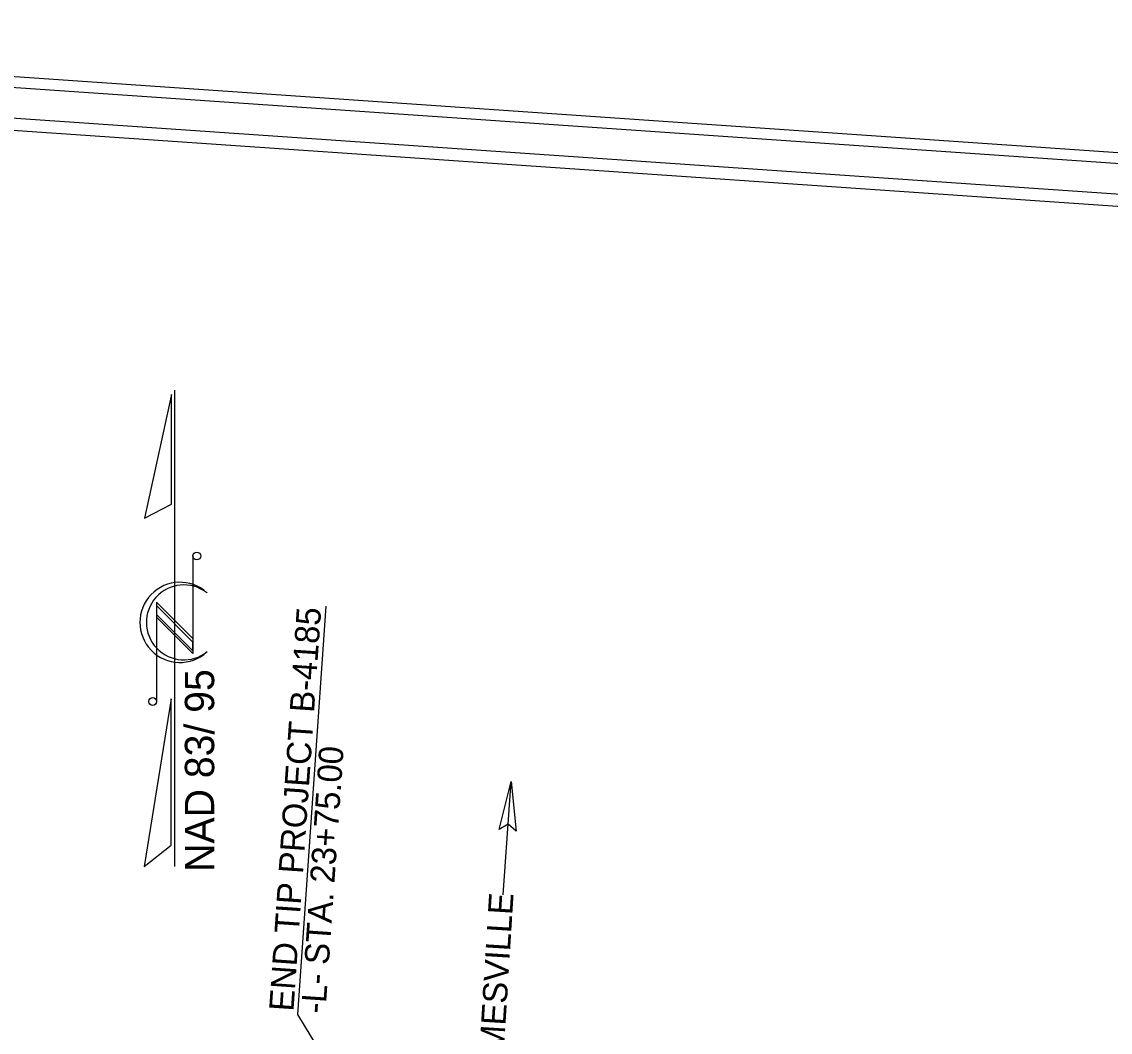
# Model space of a CAD drawing. Extents: x 2598107 to 2605763, y 726018 to 731166.
# Drawn here: x 2599109 to 2600111, y 730235 to 731166 of the extents above; entities that cross this region are included whole.
import ezdxf

# ---------------------------------------------------------------- set-up
doc = ezdxf.new("R2010")
doc.units = 0
for name, color, linetype in [('Old_Level_23', 7, 'Continuous'), ('Old_Level_38', 7, 'Continuous'), ('Old_Level_40', 7, 'Continuous'), ('Prop Terminator CELL', 7, 'Continuous'), ('Sheet North Arrow CELL', 7, 'Continuous'), ('Sheet Plot Border Inside CELL', 7, 'Continuous'), ('Sheet Plot Border Outside CELL', 7, 'Continuous'), ('Sheet Title CELL', 7, 'Continuous')]:
    doc.layers.add(name, color=color, linetype=linetype)

msp = doc.modelspace()

# ---------------------------------------------------------------- linework, layer by layer
at = {"layer": 'Old_Level_23'}
msp.add_line((2599552.1, 730361.8), (2599559.6, 730466.3), dxfattribs=at)
at = {"layer": 'Old_Level_40'}
for p, q in [((2599363.2, 730251.5), (2599389.1, 730627.7)), ((2599531.5, 729976.3), (2599363.2, 730251.5))]:
    msp.add_line(p, q, dxfattribs=at)
at = {"layer": 'Prop Terminator CELL'}
msp.add_lwpolyline([(2599548.6, 730422), (2599559.6, 730466.3), (2599564.3, 730420.6), (2599556.8, 730426.9)], close=True, dxfattribs=at)
at = {"layer": 'Sheet North Arrow CELL'}
for p, q in [((2599250, 730387.9), (2599250, 730826.7)), ((2599266.5, 730674), (2599266.5, 730584)), ((2599278.9, 730640.5), (2599279.4, 730640.1)), ((2599266.5, 730598), (2599233, 730631.5)), ((2599233, 730631.5), (2599233, 730540)), ((2599266.5, 730594.7), (2599233, 730628.2)), ((2599233, 730628.2), (2599233, 730620)), ((2599266.5, 730586.5), (2599233, 730620)), ((2599233, 730620), (2599266.5, 730586.5)), ((2599266.5, 730584), (2599233, 730617.5)), ((2599266.5, 730586.5), (2599266.5, 730594.7))]:
    msp.add_line(p, q, dxfattribs=at)
for points in [[(2599246.9, 730822.8), (2599221.9, 730708.9), (2599246.9, 730721.6)], [(2599246.4, 730542.5), (2599221.6, 730387.9), (2599246.4, 730407.5)]]:
    msp.add_lwpolyline(points, close=True, dxfattribs=at)
for centre in [(2599270.1, 730673.9), (2599229.4, 730539.9)]:
    msp.add_circle(centre, 3.58, dxfattribs=at)
for centre, radius, start, end in [((2599254.6, 730612.8), 36.9, 47.84, 312.3941), ((2599258.2, 730612.8), 34.5, 53.095, 308.6287)]:
    msp.add_arc(centre, radius, start, end, dxfattribs=at)
at = {"layer": 'Sheet Plot Border Inside CELL'}
msp.add_lwpolyline([(2600527.3, 727248.6), (2600785, 730989.4), (2598416.6, 731152.5), (2598159, 727411.7)], close=True, dxfattribs=at)
at = {"layer": 'Sheet Plot Border Outside CELL'}
msp.add_lwpolyline([(2598366.9, 731166.1), (2598106.6, 727386), (2600575.7, 727216), (2600836, 730996)], close=True, dxfattribs=at)
at = {"layer": 'Sheet Title CELL'}
for points in [[(2600754.8, 730963.3), (2598442.8, 731122.5)], [(2600327.6, 730981.4), (2598453.3, 731110.5)]]:
    msp.add_lwpolyline(points, dxfattribs=at)

# ---------------------------------------------------------------- texts
at = {"layer": 'Old_Level_23'}
msp.add_text('TO JAMESVILLE', height=22.5, rotation=86.4605, dxfattribs=at).set_placement((2599547.5, 730131))
at = {"layer": 'Old_Level_38'}
for s, p in [('END TIP PROJECT B-4185', (2599359.1, 730254)), ('-L- STA. 23+75.00 ', (2599388.5, 730251.9))]:
    msp.add_text(s, height=22.5, rotation=86.0601, dxfattribs=at).set_placement(p)
at = {"layer": 'Sheet North Arrow CELL'}
msp.add_text('NAD 83/ 95', height=27, rotation=90, dxfattribs=at).set_placement((2599286.1, 730383))

doc.saveas('drawing.dxf')
